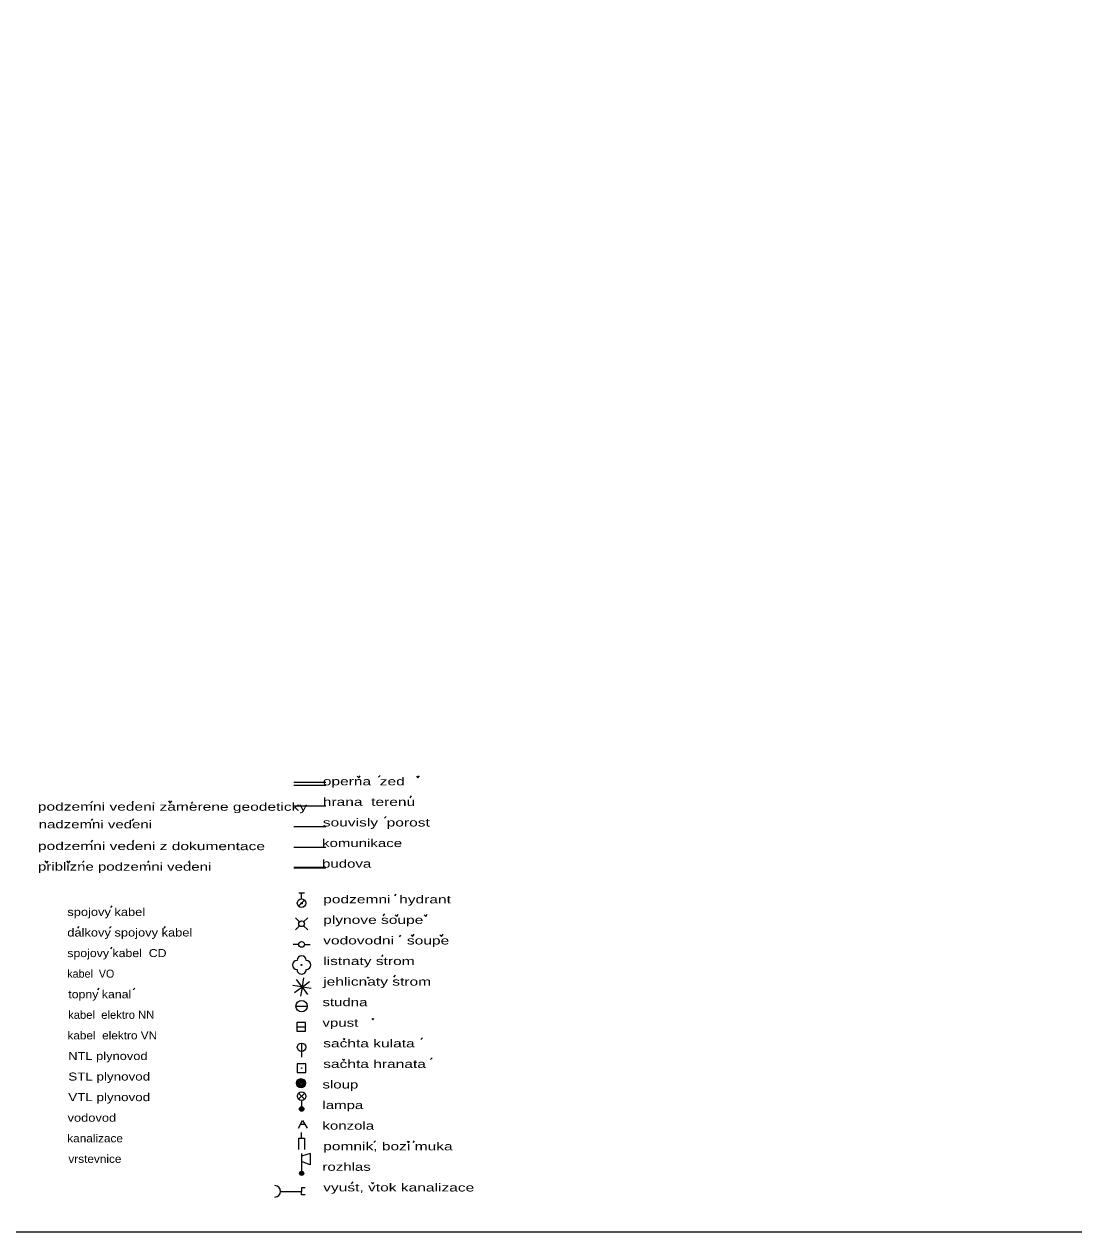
# Model space of a CAD drawing. Extents: x -670514 to -669423, y -1130798 to -1130123.
# Drawn here: x -669730.3 to -669638.5, y -1130763.5 to -1130657.9 of the extents above; entities that cross this region are included whole.
import ezdxf

# ---------------------------------------------------------------- set-up
doc = ezdxf.new("R2010")
doc.units = 0
doc.header["$LTSCALE"] = 0.24
doc.header["$PDMODE"] = 32
doc.header["$PDSIZE"] = 0.12
doc.layers.add('60', color=7, linetype='Continuous', lineweight=13)
doc.layers.add('61', color=7, linetype='Continuous', lineweight=13)

msp = doc.modelspace()

# ---------------------------------------------------------------- linework, layer by layer
at = {"layer": '60'}
msp.add_lwpolyline([(-669833.172, -1130763.536), (-669423.172, -1130763.536), (-669423.172, -1130476.536), (-669833.172, -1130476.536)], close=True, dxfattribs=at)
at = {"layer": '61'}
for p, q in [((-669703.906, -1130724.226), (-669706.695, -1130724.226)), ((-669706.695, -1130724.476), (-669703.906, -1130724.477)), ((-669699.288, -1130723.765), (-669699.155, -1130723.611)), ((-669696.53, -1130725.566), (-669696.398, -1130725.412)), ((-669724.44, -1130726.027), (-669724.307, -1130725.872)), ((-669720.835, -1130726.027), (-669720.702, -1130725.872)), ((-669715.656, -1130726.07), (-669715.524, -1130725.916)), ((-669706.695, -1130726.277), (-669703.907, -1130726.277)), ((-669724.394, -1130727.552), (-669724.262, -1130727.398)), ((-669720.825, -1130727.574), (-669720.692, -1130727.42)), ((-669698.761, -1130727.367), (-669698.629, -1130727.213)), ((-669706.695, -1130728.076), (-669703.907, -1130728.076)), ((-669724.407, -1130729.444), (-669724.275, -1130729.29)), ((-669720.802, -1130729.444), (-669720.67, -1130729.29)), ((-669706.696, -1130729.876), (-669703.907, -1130729.877)), ((-669725.164, -1130731.245), (-669725.032, -1130731.091)), ((-669719.469, -1130731.244), (-669719.337, -1130731.09)), ((-669715.932, -1130731.244), (-669715.8, -1130731.091)), ((-669706.266, -1130733.895), (-669705.767, -1130733.895)), ((-669706.017, -1130734.42), (-669706.017, -1130733.895)), ((-669697.882, -1130734.157), (-669697.751, -1130734.003)), ((-669722.706, -1130735.181), (-669722.575, -1130735.027)), ((-669706.282, -1130735.06), (-669705.752, -1130734.53)), ((-669706.548, -1130736.062), (-669706.194, -1130736.417)), ((-669705.84, -1130736.416), (-669705.486, -1130736.064)), ((-669698.889, -1130735.883), (-669698.757, -1130735.729)), ((-669725.581, -1130736.981), (-669725.45, -1130736.827)), ((-669722.799, -1130736.981), (-669722.667, -1130736.827)), ((-669718.033, -1130736.982), (-669717.902, -1130736.828)), ((-669706.194, -1130736.77), (-669706.548, -1130737.124)), ((-669705.841, -1130736.769), (-669705.487, -1130737.125)), ((-669697.473, -1130737.727), (-669697.341, -1130737.574)), ((-669722.707, -1130738.781), (-669722.576, -1130738.627)), ((-669706.268, -1130738.395), (-669706.767, -1130738.394)), ((-669705.767, -1130738.395), (-669705.268, -1130738.395)), ((-669699.014, -1130739.456), (-669698.883, -1130739.303)), ((-669705.844, -1130741.312), (-669705.971, -1130742.078)), ((-669697.943, -1130741.249), (-669697.811, -1130741.094)), ((-669723.831, -1130742.378), (-669723.7, -1130742.224)), ((-669720.731, -1130742.378), (-669720.6, -1130742.224)), ((-669706.015, -1130742.112), (-669706.781, -1130741.984)), ((-669706.638, -1130742.59), (-669706.011, -1130742.14)), ((-669706, -1130742.083), (-669706.451, -1130741.455)), ((-669705.981, -1130742.155), (-669706.108, -1130742.921)), ((-669705.954, -1130742.15), (-669705.503, -1130742.777)), ((-669705.943, -1130742.094), (-669705.315, -1130741.643)), ((-669705.172, -1130742.249), (-669705.938, -1130742.121)), ((-669706.518, -1130743.793), (-669705.517, -1130743.795)), ((-669706.439, -1130745.61), (-669705.688, -1130745.61)), ((-669695.591, -1130746.724), (-669695.459, -1130746.57)), ((-669706.017, -1130747.019), (-669706.018, -1130748.269)), ((-669694.747, -1130748.469), (-669694.616, -1130748.315)), ((-669706.28, -1130751.403), (-669705.751, -1130751.934)), ((-669706.28, -1130751.934), (-669705.75, -1130751.404)), ((-669706.016, -1130752.044), (-669706.017, -1130752.794)), ((-669705.731, -1130754.154), (-669706.134, -1130754.154)), ((-669699.695, -1130755.724), (-669699.563, -1130755.57)), ((-669696.279, -1130755.723), (-669696.147, -1130755.569)), ((-669706.017, -1130756.676), (-669706.017, -1130758.426)), ((-669705.267, -1130756.677), (-669706.017, -1130756.926)), ((-669705.267, -1130756.677), (-669705.267, -1130757.677)), ((-669705.267, -1130757.677), (-669706.018, -1130757.377)), ((-669701.643, -1130759.324), (-669701.511, -1130759.17)), ((-669707.854, -1130759.995), (-669706.017, -1130759.995)), ((-669706.017, -1130759.695), (-669706.017, -1130759.995)), ((-669705.717, -1130759.695), (-669706.017, -1130759.695)), ((-669706.017, -1130760.295), (-669706.017, -1130759.995)), ((-669705.717, -1130760.295), (-669706.017, -1130760.295))]:
    msp.add_line(p, q, dxfattribs=at)
at = {"layer": '61', "lineweight": 35}
msp.add_line((-669706.695, -1130731.677), (-669703.907, -1130731.677), dxfattribs=at)
at = {"layer": '61'}
for points in [[(-669701.157, -1130723.689), (-669701.024, -1130723.838), (-669700.893, -1130723.641)], [(-669695.986, -1130723.689), (-669695.853, -1130723.838), (-669695.722, -1130723.641)], [(-669717.667, -1130725.843), (-669717.493, -1130726.042), (-669717.361, -1130725.843)], [(-669728.47, -1130731.09), (-669728.295, -1130731.288), (-669728.163, -1130731.089)], [(-669726.563, -1130731.089), (-669726.389, -1130731.287), (-669726.257, -1130731.088)], [(-669697.834, -1130735.807), (-669697.7, -1130735.956), (-669697.569, -1130735.759)], [(-669695.294, -1130735.813), (-669695.169, -1130735.956), (-669695.038, -1130735.757)], [(-669696.435, -1130737.569), (-669696.315, -1130737.703), (-669696.184, -1130737.506)], [(-669693.929, -1130737.544), (-669693.788, -1130737.704), (-669693.657, -1130737.506)], [(-669700.298, -1130741.251), (-669700.199, -1130741.362), (-669700.124, -1130741.25)], [(-669699.883, -1130744.877), (-669699.784, -1130744.988), (-669699.709, -1130744.876)], [(-669702.385, -1130746.635), (-669702.286, -1130746.746), (-669702.211, -1130746.634)], [(-669702.442, -1130748.427), (-669702.325, -1130748.558), (-669702.239, -1130748.428)], [(-669706.296, -1130754.454), (-669705.946, -1130753.805), (-669705.546, -1130754.455)], [(-669706.266, -1130756.334), (-669706.266, -1130755.334), (-669706.017, -1130755.334), (-669706.016, -1130754.834)], [(-669706.017, -1130755.334), (-669705.766, -1130755.334), (-669705.766, -1130756.334)], [(-669696.791, -1130755.611), (-669696.674, -1130755.742), (-669696.588, -1130755.612)], [(-669699.908, -1130759.211), (-669699.791, -1130759.342), (-669699.705, -1130759.212)]]:
    msp.add_lwpolyline(points, dxfattribs=at)
for points in [[(-669706.439, -1130745.984), (-669705.689, -1130745.985), (-669705.688, -1130745.235), (-669706.438, -1130745.234)], [(-669706.393, -1130749.59), (-669705.644, -1130749.59), (-669705.643, -1130748.841), (-669706.393, -1130748.84)]]:
    msp.add_lwpolyline(points, close=True, dxfattribs=at)
for centre, radius in [((-669706.0168, -1130734.7948), 0.375), ((-669706.0169, -1130736.5938), 0.25), ((-669706.0177, -1130738.3949), 0.25), ((-669706.017, -1130740.1942), 0.04), ((-669705.9766, -1130742.1168), 0.04), ((-669706.0174, -1130743.7939), 0.5), ((-669706.0167, -1130747.3948), 0.375), ((-669706.0181, -1130749.2151), 0.02), ((-669706.0656, -1130750.5363), 0.4), ((-669706.0656, -1130750.5363), 0.32), ((-669706.0656, -1130750.5363), 0.24), ((-669706.0656, -1130750.5363), 0.16), ((-669706.0656, -1130750.5363), 0.08), ((-669706.0155, -1130751.6689), 0.375), ((-669706.0165, -1130752.794), 0.2), ((-669706.0165, -1130752.794), 0.1445), ((-669706.0165, -1130752.794), 0.0876), ((-669706.0172, -1130758.4264), 0.18), ((-669706.0172, -1130758.4264), 0.1)]:
    msp.add_circle(centre, radius, dxfattribs=at)
for centre, radius, start, end in [((-669706.417, -1130740.1942), 0.4, 90.01303, 270.01303), ((-669706.0171, -1130739.7942), 0.4, 0.01303, 180.01303), ((-669705.617, -1130740.1941), 0.4, 270.01303, 90.01303), ((-669706.0169, -1130740.5942), 0.4, 180.01303, 0.01303), ((-669708.354, -1130759.9955), 0.5, 270, 90)]:
    msp.add_arc(centre, radius, start, end, dxfattribs=at)
msp.add_point((-669706.017, -1130734.795), dxfattribs=at)

# ---------------------------------------------------------------- texts
for s, rotation, width, p in [('     operna  zed', 359.949, 1.45, (-669706.052, -1130724.475)), ('     hrana  terenu', 359.949, 1.45, (-669706.051, -1130726.275)), ('podzemni vedeni zamerene geodeticky', 359.949, 1.45, (-669729.077, -1130726.691)), ('nadzemni vedeni', 359.949, 1.4, (-669728.998, -1130728.237)), ('     souvisly  porost', 359.949, 1.45, (-669706.051, -1130728.076)), ('podzemni vedeni z dokumentace', 359.949, 1.45, (-669729.063, -1130730.136)), ('     komunikace', 359.949, 1.4, (-669706.05, -1130729.876)), ('priblizne podzemni vedeni', 359.949, 1.4, (-669729.063, -1130731.937)), ('     budova', 359.949, 1.4, (-669706.049, -1130731.676)), ('     podzemni  hydrant', 359.949, 1.45, (-669706.017, -1130734.795)), ('spojovy kabel', 0.01, 1.2, (-669726.497, -1130735.908)), ('     plynove soupe', 359.949, 1.45, (-669706.017, -1130736.594)), ('dalkovy spojovy kabel', 0.01, 1.2, (-669726.498, -1130737.706)), ('     vodovodni   soupe', 359.949, 1.45, (-669706.017, -1130738.395)), ('spojovy kabel  CD', 0.01, 1.15, (-669726.499, -1130739.506)), ('     listnaty strom', 359.949, 1.45, (-669706.017, -1130740.194)), ('     jehlicnaty strom', 359.949, 1.45, (-669706.017, -1130741.994)), ('topny kanal', 0.01, 1.15, (-669726.414, -1130743.104)), ('     studna', 359.949, 1.4, (-669706.017, -1130743.794)), ('kabel  elektro NN', 0.01, 1.05, (-669726.428, -1130744.903)), ('     vpust', 359.949, 1.4, (-669706.017, -1130745.594)), ('kabel  elektro VN', 0.01, 1.1, (-669726.488, -1130746.703)), ('     sachta kulata', 359.949, 1.45, (-669706.017, -1130747.395)), ('NTL plynovod', 0.01, 1.2, (-669726.414, -1130748.505)), ('     sachta hranata', 359.949, 1.45, (-669706.017, -1130749.194)), ('STL plynovod', 0.01, 1.25, (-669726.414, -1130750.304)), ('     sloup', 359.949, 1.4, (-669706.017, -1130750.995)), ('VTL plynovod', 0.01, 1.25, (-669726.414, -1130752.105)), ('     lampa', 359.949, 1.4, (-669706.017, -1130752.794)), ('vodovod', 0.01, 1.2, (-669726.475, -1130753.905)), ('     konzola', 359.949, 1.4, (-669706.017, -1130754.594)), ('kanalizace', 0.01, 1.1, (-669726.501, -1130755.704)), ('     pomnik, bozi muka', 359.949, 1.45, (-669706.017, -1130756.395)), ('vrstevnice', 0.01, 1.1, (-669726.403, -1130757.503)), ('     rozhlas', 359.949, 1.4, (-669706.017, -1130758.194)), ('     vyust, vtok kanalizace', 359.949, 1.45, (-669706.017, -1130759.995))]:
    msp.add_text(s, height=0.7, rotation=rotation, dxfattribs=dict(at, width=width)).set_placement(p)
msp.add_text('kabel  VO', height=0.7, rotation=0.01, dxfattribs=at).set_placement((-669726.5, -1130741.304))

doc.saveas('drawing.dxf')
